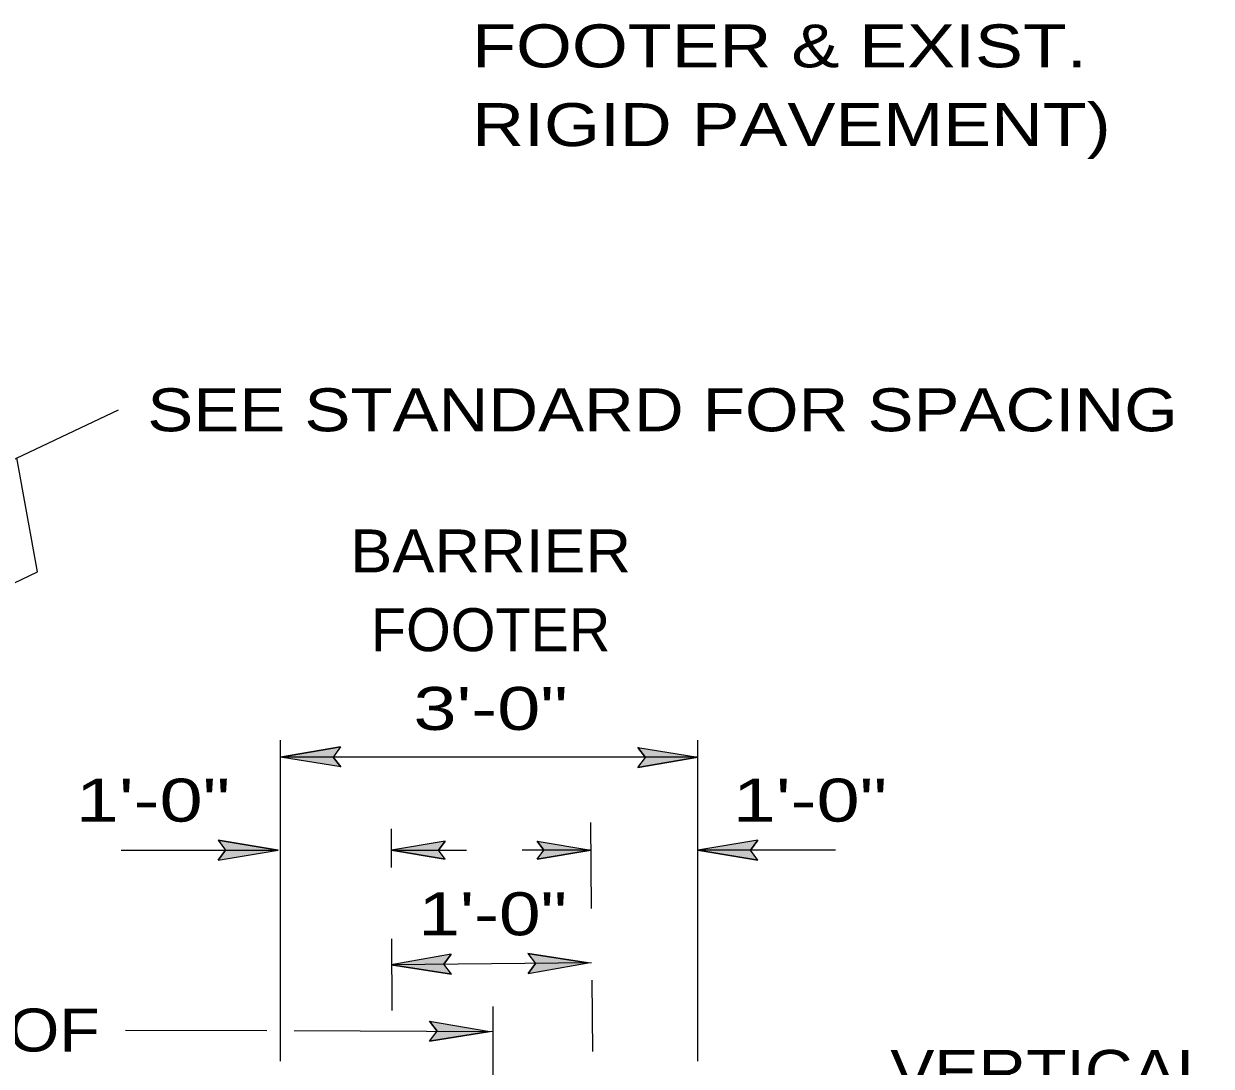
# Model space of a CAD drawing. Extents: x -11.7 to -4.5, y 8.6 to 18.8.
# Drawn here: x -6.272 to -4.613, y 13.617 to 15.073 of the extents above; entities that cross this region are included whole.
import ezdxf
from ezdxf.enums import TextEntityAlignment as Align

# ---------------------------------------------------------------- set-up
doc = ezdxf.new("R2010")
doc.units = 0
doc.header["$LTSCALE"] = 0.024
doc.linetypes.add('DOT_DASHED', pattern=[7.7, 5, -1.2, 0.3, -1.2])
doc.layers.add('10', color=7, linetype='Continuous', lineweight=13)
doc.layers.add('12', color=7, linetype='Continuous', lineweight=53)

msp = doc.modelspace()

# ---------------------------------------------------------------- hatches: boundary and pattern name
at = {"layer": '10'}
for points in [[(-5.83967, 14.0485), (-5.829, 14.03467), (-5.91317, 14.04817), (-5.82917, 14.06267)], [(-5.33, 14.04817), (-5.414, 14.03367), (-5.4035, 14.04767), (-5.41417, 14.06167)], [(-5.91633, 13.91833), (-6.00033, 13.93233), (-5.99, 13.91833), (-6.00033, 13.90433)], [(-5.33017, 13.91833), (-5.24617, 13.90433), (-5.25667, 13.91833), (-5.24617, 13.93233)], [(-5.683, 13.93083), (-5.758, 13.91833), (-5.683, 13.90583), (-5.6925, 13.91833)], [(-5.47967, 13.91833), (-5.55467, 13.90583), (-5.54533, 13.91833), (-5.55467, 13.93083)], [(-5.7585, 13.75817), (-5.67433, 13.745), (-5.685, 13.759), (-5.67467, 13.773)], [(-5.56733, 13.746), (-5.4835, 13.76083), (-5.56767, 13.774), (-5.557, 13.76017)], [(-5.62083, 13.66533), (-5.70483, 13.65167), (-5.69433, 13.6655), (-5.70483, 13.67967)]]:
    msp.add_hatch(color=256, dxfattribs=at).paths.add_polyline_path(points)

# ---------------------------------------------------------------- linework, layer by layer
for p, q in [((-6.35617, 14.43083), (-6.13917, 14.5335)), ((-5.91317, 13.62383), (-5.91317, 14.07217)), ((-5.33017, 13.62383), (-5.33017, 14.07217)), ((-5.82917, 14.06267), (-5.91317, 14.04817)), ((-5.829, 14.03467), (-5.91317, 14.04817)), ((-5.33, 14.04817), (-5.91317, 14.04817)), ((-5.82917, 14.06267), (-5.83967, 14.0485)), ((-5.829, 14.03467), (-5.83967, 14.0485)), ((-5.41417, 14.06167), (-5.33, 14.04817)), ((-5.41417, 14.06167), (-5.4035, 14.04767)), ((-5.414, 14.03367), (-5.33, 14.04817)), ((-5.414, 14.03367), (-5.4035, 14.04767)), ((-6.00033, 13.93233), (-5.91633, 13.91833)), ((-6.00033, 13.93233), (-5.99, 13.91833)), ((-5.24617, 13.93233), (-5.33017, 13.91833)), ((-5.24617, 13.93233), (-5.25667, 13.91833)), ((-6.1355, 13.91833), (-5.91633, 13.91833)), ((-6.00033, 13.90433), (-5.91633, 13.91833)), ((-6.00033, 13.90433), (-5.99, 13.91833)), ((-5.683, 13.93083), (-5.758, 13.91833)), ((-5.758, 13.91833), (-5.65317, 13.91833)), ((-5.683, 13.90583), (-5.758, 13.91833)), ((-5.683, 13.93083), (-5.6925, 13.91833)), ((-5.683, 13.90583), (-5.6925, 13.91833)), ((-5.47967, 13.91833), (-5.57533, 13.91833)), ((-5.55467, 13.93083), (-5.47967, 13.91833)), ((-5.55467, 13.93083), (-5.54533, 13.91833)), ((-5.55467, 13.90583), (-5.47967, 13.91833)), ((-5.55467, 13.90583), (-5.54533, 13.91833)), ((-5.13783, 13.91833), (-5.33017, 13.91833)), ((-5.24617, 13.90433), (-5.33017, 13.91833)), ((-5.24617, 13.90433), (-5.25667, 13.91833)), ((-5.67467, 13.773), (-5.7585, 13.75817)), ((-5.67467, 13.773), (-5.685, 13.759)), ((-5.56767, 13.774), (-5.4835, 13.76083)), ((-5.56767, 13.774), (-5.557, 13.76017)), ((-5.67433, 13.745), (-5.7585, 13.75817)), ((-5.47867, 13.761), (-5.75783, 13.75817)), ((-5.67433, 13.745), (-5.685, 13.759)), ((-5.56733, 13.746), (-5.4835, 13.76083)), ((-5.56733, 13.746), (-5.557, 13.76017)), ((-6.1295, 13.66717), (-5.93217, 13.6665)), ((-5.70483, 13.67967), (-5.62083, 13.66533)), ((-5.70483, 13.67967), (-5.69433, 13.6655)), ((-5.89383, 13.66633), (-5.61683, 13.66533)), ((-5.70483, 13.65167), (-5.69433, 13.6655)), ((-5.70483, 13.65167), (-5.62083, 13.66533))]:
    msp.add_line(p, q, dxfattribs=at)
at = {"layer": '10', "linetype": 'DOT_DASHED'}
for p, q in [((-5.48, 13.957), (-5.47467, 13.31633)), ((-5.7565, 13.47433), (-5.75817, 13.94817)), ((-5.61667, 13.69983), (-5.61633, 13.1925))]:
    msp.add_line(p, q, dxfattribs=at)
at = {"layer": '10'}
msp.add_lwpolyline([(-6.32717, 14.27183), (-6.25233, 14.30733), (-6.28133, 14.46617)], dxfattribs=at)
for points in [[(-5.83967, 14.0485), (-5.829, 14.03467), (-5.91317, 14.04817), (-5.82917, 14.06267)], [(-5.33, 14.04817), (-5.414, 14.03367), (-5.4035, 14.04767), (-5.41417, 14.06167)], [(-5.91633, 13.91833), (-6.00033, 13.93233), (-5.99, 13.91833), (-6.00033, 13.90433)], [(-5.33017, 13.91833), (-5.24617, 13.90433), (-5.25667, 13.91833), (-5.24617, 13.93233)], [(-5.683, 13.93083), (-5.758, 13.91833), (-5.683, 13.90583), (-5.6925, 13.91833)], [(-5.47967, 13.91833), (-5.55467, 13.90583), (-5.54533, 13.91833), (-5.55467, 13.93083)], [(-5.7585, 13.75817), (-5.67433, 13.745), (-5.685, 13.759), (-5.67467, 13.773)], [(-5.56733, 13.746), (-5.4835, 13.76083), (-5.56767, 13.774), (-5.557, 13.76017)], [(-5.62083, 13.66533), (-5.70483, 13.65167), (-5.69433, 13.6655), (-5.70483, 13.67967)]]:
    msp.add_lwpolyline(points, close=True, dxfattribs=at)

# ---------------------------------------------------------------- texts
at = {"layer": '12'}
for s, width, p in [('FOOTER & EXIST.', 1.25, (-5.64533, 15.01175)), ('RIGID PAVEMENT)', 1.25, (-5.64533, 14.90175)), ('SEE STANDARD FOR SPACING', 1.2, (-6.09908, 14.50342)), ('C OF', 1.15, (-6.386, 13.63717)), ('VERTICAL', 1.15, (-5.06133, 13.57933))]:
    msp.add_text(s, height=0.06001, dxfattribs=dict(at, width=width)).set_placement(p)
for s, width, p in [('BARRIER', 1.1, (-5.61954, 14.30633)), ('3\'-0"', 1.35, (-5.61958, 14.08633)), ('1\'-0"', 1.35, (-6.09117, 13.95825)), ('1\'-0"', 1.35, (-5.17358, 13.95825)), ('1\'-0"', 1.3, (-5.61667, 13.7995))]:
    msp.add_text(s, height=0.06001, dxfattribs=dict(at, width=width)).set_placement(p, align=Align.CENTER)
msp.add_text('FOOTER', height=0.06001, dxfattribs=at).set_placement((-5.61954, 14.19633), align=Align.CENTER)

doc.saveas('drawing.dxf')
